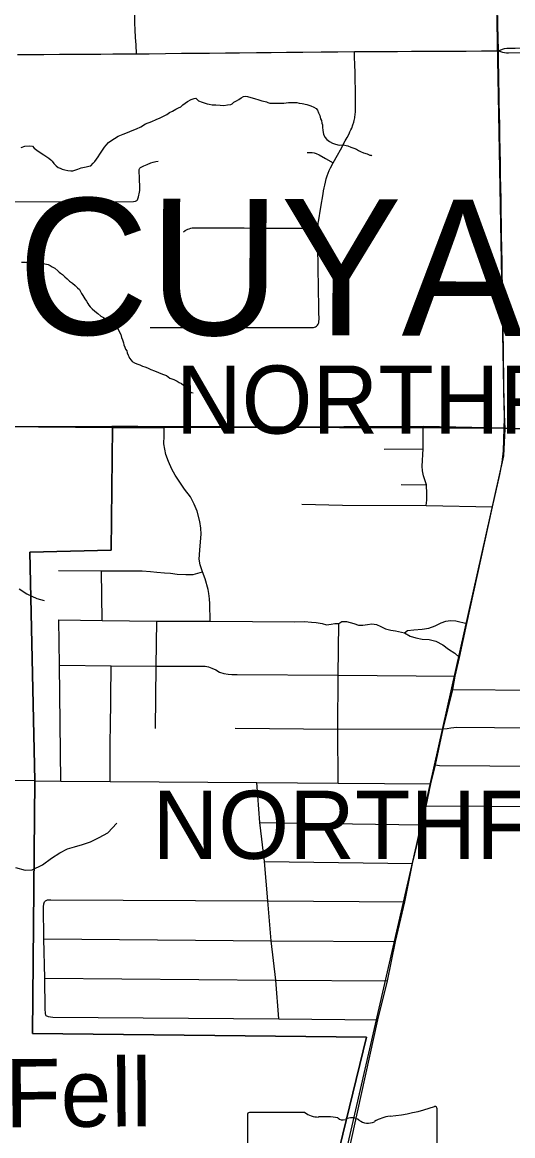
# Model space of a CAD drawing. Extents: x 0 to 34, y 0 to 22.
# Drawn here: x 3.992 to 4.674, y 14.366 to 15.914 of the extents above; entities that cross this region are included whole.
import ezdxf

# ---------------------------------------------------------------- set-up
doc = ezdxf.new("R2010")
doc.units = 0
for name, color, linetype in [('GM_X_City_Street', 7, 'Continuous'), ('GM_X_Corporation_Text', 7, 'Continuous'), ('GM_X_County_Road', 7, 'Continuous'), ('GM_X_County_Text', 7, 'Continuous'), ('GM_X_Minor_Lake_Text', 7, 'Continuous'), ('GM_X_Minor_River', 7, 'Continuous'), ('GM_X_Rail_Line', 7, 'Continuous'), ('GM_X_State_Route', 7, 'Continuous'), ('GM_X_State_Shield', 7, 'Continuous'), ('GM_X_Township_Road', 7, 'Continuous'), ('SH_Cut_Line', 7, 'Continuous')]:
    doc.layers.add(name, color=color, linetype=linetype)

msp = doc.modelspace()

# ---------------------------------------------------------------- linework, layer by layer
at = {"layer": 'GM_X_City_Street'}
for p, q in [((4.4951, 15.3209), (4.5493, 15.3211)), ((4.5189, 15.2716), (4.5539, 15.2711)), ((4.1025, 15.0825), (4.1017, 15.1517)), ((4.5905, 14.9868), (5.0641, 14.9831)), ((4.3223, 14.8018), (4.5473, 14.7985)), ((4.3287, 14.7474), (4.5346, 14.7449))]:
    msp.add_line(p, q, dxfattribs=at)
for points in [[(4.1505, 15.8705), (4.1498, 15.8829), (4.1492, 15.893), (4.1487, 15.9038), (4.1484, 15.913), (4.148, 15.9252), (4.1475, 15.9384), (4.1472, 15.9495), (4.1468, 15.9654), (4.1465, 15.9801), (4.1462, 15.9917), (4.1459, 16.0043), (4.1456, 16.0183), (4.1454, 16.0261), (4.1452, 16.028), (4.145, 16.0299), (4.1446, 16.0317), (4.144, 16.0335), (4.1434, 16.0347), (4.1428, 16.0358), (4.142, 16.0368), (4.1411, 16.0377), (4.1401, 16.0385)], [(4.4021, 15.493), (4.4031, 15.4944), (4.4036, 15.4955), (4.404, 15.4966), (4.4043, 15.4988), (4.4044, 15.5012), (4.4043, 15.5116), (4.4041, 15.5248), (4.4038, 15.5375), (4.4036, 15.5514), (4.4033, 15.5665), (4.403, 15.5815), (4.4027, 15.5937), (4.4025, 15.606), (4.4023, 15.6157), (4.4024, 15.6251), (4.4025, 15.6278), (4.4027, 15.6305), (4.403, 15.6327), (4.4032, 15.6348), (4.4035, 15.637), (4.4069, 15.6571), (4.4101, 15.6758), (4.4108, 15.6799), (4.4115, 15.684), (4.4123, 15.688), (4.4133, 15.6922), (4.4145, 15.6967), (4.4157, 15.7007), (4.4171, 15.7046), (4.4186, 15.7083), (4.4203, 15.7119), (4.424, 15.7187), (4.4299, 15.7296), (4.4341, 15.7371), (4.441, 15.7493), (4.4437, 15.7542), (4.4463, 15.7592), (4.4475, 15.7619), (4.4487, 15.7645), (4.4499, 15.7672), (4.4516, 15.7718), (4.4527, 15.7756), (4.4532, 15.7775), (4.4537, 15.7794), (4.4541, 15.7814), (4.4544, 15.7832), (4.4546, 15.785), (4.4549, 15.7868), (4.455, 15.7886), (4.4551, 15.7904), (4.4552, 15.7922), (4.4553, 15.7971), (4.4551, 15.8221), (4.4548, 15.8324), (4.4545, 15.8439), (4.4543, 15.8554), (4.454, 15.8656), (4.4539, 15.8734)], [(4.3879, 15.733), (4.3924, 15.7331), (4.3951, 15.733), (4.3975, 15.7327), (4.399, 15.7324), (4.4004, 15.7319), (4.4045, 15.7299), (4.4133, 15.7248), (4.424, 15.7187)], [(3.9667, 15.6647), (4.1461, 15.6652), (4.1491, 15.6655), (4.15, 15.6659), (4.1509, 15.6666), (4.1517, 15.6675), (4.1523, 15.6687), (4.1531, 15.6715), (4.1545, 15.678), (4.1549, 15.6804), (4.155, 15.6833), (4.1545, 15.6983), (4.1541, 15.7066), (4.1542, 15.7095), (4.1547, 15.7105), (4.1553, 15.7115), (4.1561, 15.7122), (4.1569, 15.7128), (4.1609, 15.7148), (4.1651, 15.7167), (4.1702, 15.7187), (4.1736, 15.7198), (4.1756, 15.7203), (4.1776, 15.7206), (4.1808, 15.721)], [(4.2158, 15.6229), (4.2183, 15.6247), (4.2201, 15.6257), (4.222, 15.6266), (4.2239, 15.6273), (4.2259, 15.6279), (4.2279, 15.6283), (4.2299, 15.6286), (4.234, 15.6287), (4.2471, 15.6286), (4.2639, 15.6285), (4.2822, 15.6284), (4.3001, 15.6283), (4.3162, 15.6282), (4.335, 15.6281), (4.3534, 15.628), (4.3721, 15.6279), (4.3884, 15.6278), (4.4025, 15.6278)], [(4.1694, 15.4901), (4.3947, 15.4898), (4.3966, 15.4901), (4.398, 15.4905), (4.3994, 15.491), (4.4008, 15.4918), (4.4021, 15.493)], [(4.2529, 15.0816), (4.2524, 15.1058), (4.252, 15.1125), (4.2513, 15.1201), (4.25, 15.1259), (4.246, 15.1403), (4.2422, 15.1501), (4.239, 15.1599), (4.2376, 15.1679), (4.2385, 15.1804), (4.2396, 15.1921), (4.2406, 15.2027), (4.2399, 15.2108), (4.2387, 15.2202), (4.235, 15.2345), (4.2307, 15.2442), (4.2254, 15.2543), (4.2173, 15.2651), (4.2044, 15.2845), (4.1996, 15.2928), (4.195, 15.3036), (4.1913, 15.3133), (4.1899, 15.3209), (4.1887, 15.3283), (4.1891, 15.3391), (4.1889, 15.3522)], [(4.5534, 15.2424), (4.5543, 15.2499), (4.5546, 15.2587), (4.5539, 15.2711), (4.5497, 15.2836), (4.5482, 15.2909), (4.5478, 15.2971), (4.5493, 15.3211), (4.5495, 15.3508)], [(4.3806, 15.2442), (4.4371, 15.2428), (4.5534, 15.2424), (4.646, 15.2405)], [(4.0418, 15.1521), (4.1017, 15.1517), (4.1586, 15.1517), (4.1699, 15.1508), (4.179, 15.1497), (4.1893, 15.149), (4.1977, 15.1485), (4.2071, 15.1472), (4.2191, 15.1465), (4.2291, 15.1465), (4.2422, 15.1501)], [(4.0423, 15.0834), (4.1025, 15.0825), (4.1788, 15.0816), (4.2529, 15.0816), (4.371, 15.0806), (4.3841, 15.0811), (4.3938, 15.0804), (4.4005, 15.0797), (4.4086, 15.0784), (4.4147, 15.0767), (4.4212, 15.0776), (4.4265, 15.0785), (4.4322, 15.0785), (4.4362, 15.0811), (4.4428, 15.0813), (4.4527, 15.0783), (4.4592, 15.076), (4.4652, 15.0762), (4.4719, 15.0769), (4.4779, 15.0778), (4.4843, 15.0769), (4.4903, 15.0744), (4.497, 15.0712), (4.5041, 15.0691), (4.5108, 15.0684), (4.5235, 15.0656), (4.5313, 15.061), (4.5391, 15.0583), (4.5477, 15.0566), (4.5576, 15.056), (4.5668, 15.0539), (4.5767, 15.049), (4.5845, 15.0428), (4.5935, 15.0371), (4.5999, 15.0311)], [(4.0452, 14.8592), (4.0432, 15.0204), (4.0423, 15.0834)], [(4.177, 14.9324), (4.1779, 15.0193), (4.1788, 15.0816)], [(4.4312, 14.8565), (4.4306, 14.9317), (4.431, 15.0064), (4.4322, 15.0785)], [(4.5235, 15.0656), (4.5274, 15.0686), (4.5361, 15.0698), (4.5479, 15.0705), (4.5571, 15.0721), (4.5661, 15.0751), (4.5744, 15.0792), (4.5808, 15.0815), (4.5875, 15.0827), (4.5947, 15.082), (4.6101, 15.0783)], [(4.0432, 15.0204), (4.1152, 15.0198), (4.1779, 15.0193), (4.2462, 15.0189), (4.2506, 15.018), (4.2553, 15.0164), (4.2607, 15.0138), (4.266, 15.0107), (4.272, 15.0087), (4.2778, 15.0078), (4.2831, 15.0075), (4.2907, 15.0073), (4.431, 15.0064), (4.594, 15.005)], [(4.1139, 14.8586), (4.1137, 14.9188), (4.1141, 14.931), (4.1152, 15.0198)], [(4.2878, 14.9331), (4.4306, 14.9317), (4.5771, 14.9322)], [(4.5771, 14.9322), (4.5829, 14.9325), (4.588, 14.9334), (4.596, 14.9343), (5.0664, 14.93)], [(4.5664, 14.8821), (4.5722, 14.8812), (4.7121, 14.8799), (4.8933, 14.879), (5.0666, 14.8763)], [(4.0094, 14.8598), (4.0452, 14.8592), (4.1139, 14.8586), (4.318, 14.8573), (4.4312, 14.8565), (4.5598, 14.8557)], [(4.3483, 14.5288), (4.3443, 14.5828), (4.3378, 14.6373), (4.3334, 14.6927), (4.3287, 14.7474), (4.3223, 14.8018), (4.318, 14.8573)], [(4.856, 14.5164), (4.8055, 14.5161), (4.8008, 14.5165), (4.7966, 14.517), (4.7908, 14.5192), (4.7859, 14.5221), (4.7821, 14.5265), (4.7801, 14.5321), (4.7799, 14.5392), (4.781, 14.6406), (4.7817, 14.7651), (4.7813, 14.7758), (4.7799, 14.7834), (4.7773, 14.7907), (4.7748, 14.7947), (4.7708, 14.8014), (4.7646, 14.8083), (4.7592, 14.8127), (4.7517, 14.817), (4.7437, 14.8205), (4.7357, 14.8223), (4.7245, 14.8234), (4.5535, 14.8247)], [(4.0245, 14.5334), (4.0238, 14.5368), (4.0234, 14.5421), (4.0229, 14.5852), (4.0214, 14.6399), (4.0209, 14.6844), (4.0216, 14.6886), (4.0223, 14.6913), (4.024, 14.6931)], [(4.024, 14.6931), (4.0269, 14.6942), (4.0312, 14.6944), (4.3334, 14.6927), (4.524, 14.6913)], [(4.0214, 14.6399), (4.3378, 14.6373), (4.5108, 14.6362)], [(4.0229, 14.5852), (4.3443, 14.5828), (4.4995, 14.5817)], [(4.0245, 14.5334), (4.0278, 14.5323), (4.0309, 14.5316), (4.0343, 14.5312), (4.3483, 14.5288), (4.4864, 14.5275)]]:
    msp.add_lwpolyline(points, dxfattribs=at)
at = {"layer": 'GM_X_County_Road'}
msp.add_line((4.1523, 15.3526), (4.1549, 15.3525), dxfattribs=at)
for points in [[(3.985, 15.8693), (4.0039, 15.8694), (4.0217, 15.8695), (4.0434, 15.8697), (4.0632, 15.8698), (4.081, 15.87), (4.101, 15.8701), (4.1176, 15.8702), (4.1381, 15.8704), (4.1505, 15.8705), (4.168, 15.8706), (4.1908, 15.8709), (4.213, 15.8711), (4.2332, 15.8713), (4.2522, 15.8714), (4.2743, 15.8717), (4.294, 15.8719), (4.3176, 15.8721), (4.3378, 15.8723), (4.3593, 15.8725), (4.3818, 15.8727), (4.4075, 15.873), (4.4307, 15.8732), (4.4539, 15.8734), (4.4736, 15.8735), (4.4929, 15.8736), (4.5135, 15.8738), (4.533, 15.8739), (4.5539, 15.874), (4.5741, 15.8741), (4.5914, 15.8742), (4.609, 15.8743), (4.6303, 15.8745), (4.654, 15.8746)], [(4.654, 15.8746), (4.6596, 15.877), (4.6624, 15.8779), (4.6655, 15.8783), (4.6775, 15.8784), (4.6955, 15.8785), (4.7114, 15.8786), (4.7292, 15.8787), (4.7462, 15.8788), (4.7626, 15.8789), (4.779, 15.879), (4.7958, 15.8792), (4.8137, 15.8793), (4.9176, 15.8796), (4.9411, 15.8797), (4.9626, 15.8797)], [(4.654, 15.8746), (4.6598, 15.8727), (4.6626, 15.8722), (4.6652, 15.8719), (4.6682, 15.8717), (4.8136, 15.8721), (4.9446, 15.8724), (4.9655, 15.8725)], [(3.8085, 15.3532), (3.8384, 15.3529), (3.8832, 15.3532), (3.9221, 15.3531), (3.9719, 15.3528), (4.032, 15.3522), (4.1163, 15.3526), (4.1523, 15.3526)], [(4.1549, 15.3525), (4.1567, 15.3525), (4.1806, 15.3522), (4.1889, 15.3522)], [(4.1889, 15.3522), (4.271, 15.3523), (4.3262, 15.3519), (4.3455, 15.3517), (4.3666, 15.3516), (4.3963, 15.3514), (4.4329, 15.351), (4.5495, 15.3508)], [(4.5495, 15.3508), (4.5819, 15.3506), (4.6282, 15.3504), (4.6622, 15.3502)]]:
    msp.add_lwpolyline(points, dxfattribs=at)
at = {"layer": 'GM_X_County_Text'}
for points in [[(2.1, 20.9), (2.1, 15.3556), (2.5967, 15.3568), (2.8413, 15.3568), (3.0143, 15.3554), (3.32, 15.3518), (3.6529, 15.3542), (3.8077, 15.3535), (4.1171, 15.3509), (4.1892, 15.3509), (4.3286, 15.3514), (4.5491, 15.3522), (4.6624, 15.3501), (5.0644, 15.3373), (5.4203, 15.3364), (5.4506, 15.3363), (5.4723, 15.3363), (5.5032, 15.3362), (5.5738, 15.336), (5.6184, 15.3359), (5.911, 15.3352), (6.0514, 15.3349), (6.6171, 15.3291), (8.9, 15.3047)], [(5.0601, 14.3351), (5.0736, 14.8415), (5.0745, 14.9887), (5.0644, 15.3373), (4.6624, 15.3501), (4.5491, 15.3522), (4.3286, 15.3514), (4.1892, 15.3509), (4.1171, 15.3509), (4.1154, 15.1803), (4.002, 15.1777), (4.0092, 14.8604), (4.0058, 14.5086), (4.4707, 14.5032), (4.4185, 14.2906)]]:
    msp.add_lwpolyline(points, dxfattribs=at)
msp.add_lwpolyline([(2.1, 15.3556), (2.1, 14.1), (4.3787, 14.1), (4.3725, 14.1373), (4.3676, 14.1533), (4.4185, 14.2906), (4.4707, 14.5032), (4.0058, 14.5086), (4.0092, 14.8604), (4.002, 15.1777), (4.1154, 15.1803), (4.1171, 15.3509), (3.8077, 15.3535), (3.6529, 15.3542), (3.32, 15.3518), (3.0143, 15.3554), (2.8413, 15.3568), (2.5967, 15.3568)], close=True, dxfattribs=at)
at = {"layer": 'GM_X_Minor_River'}
for points in [[(4.1059, 15.7406), (4.1081, 15.7433), (4.1115, 15.7472), (4.116, 15.7503), (4.1201, 15.7526), (4.125, 15.7561), (4.1318, 15.7588), (4.1378, 15.7612), (4.1443, 15.7639), (4.1507, 15.7663), (4.1567, 15.769), (4.1631, 15.7733), (4.1718, 15.7761), (4.1778, 15.7792), (4.1835, 15.7815), (4.188, 15.7839), (4.1925, 15.7862), (4.1963, 15.7886), (4.2005, 15.7909), (4.205, 15.7936), (4.2091, 15.7952), (4.2121, 15.7967), (4.2151, 15.7994), (4.2215, 15.8041), (4.2264, 15.8068), (4.2306, 15.8084), (4.2329, 15.8088), (4.2367, 15.805), (4.2417, 15.8032), (4.2462, 15.8017), (4.2489, 15.801), (4.2516, 15.8003), (4.2558, 15.7996), (4.2607, 15.7993), (4.2671, 15.799), (4.2721, 15.7986), (4.277, 15.7995), (4.2816, 15.7999), (4.2834, 15.8007), (4.2861, 15.803), (4.2898, 15.805), (4.2928, 15.8069), (4.2959, 15.8092), (4.2992, 15.8112), (4.3027, 15.8116), (4.3049, 15.8112), (4.316, 15.808), (4.3194, 15.8069), (4.3221, 15.8061), (4.3247, 15.805), (4.3274, 15.8047), (4.3293, 15.8039), (4.3312, 15.8036), (4.3331, 15.8025), (4.3362, 15.8017), (4.3392, 15.8018), (4.3426, 15.8018), (4.3487, 15.8019), (4.3555, 15.802), (4.362, 15.8025), (4.3677, 15.8025), (4.3707, 15.8029), (4.3734, 15.8026), (4.3768, 15.8019), (4.381, 15.8012), (4.3874, 15.8001), (4.3931, 15.7983), (4.3973, 15.7964), (4.4004, 15.7946), (4.4023, 15.7919), (4.4039, 15.7885), (4.4055, 15.7848), (4.4067, 15.7802), (4.4078, 15.7776), (4.4083, 15.7741), (4.4091, 15.7715), (4.4091, 15.7684), (4.4095, 15.7639), (4.4107, 15.7586), (4.4127, 15.7544), (4.4154, 15.7514), (4.4188, 15.7484), (4.4234, 15.7462), (4.4272, 15.7447), (4.4326, 15.7436), (4.4379, 15.7437), (4.4447, 15.7423), (4.4485, 15.7408), (4.4527, 15.7393), (4.4565, 15.7379), (4.4592, 15.736), (4.4623, 15.7345), (4.4661, 15.7327), (4.4714, 15.7312), (4.4749, 15.7297), (4.4768, 15.7294), (4.4779, 15.7286)], [(3.9901, 15.7403), (3.995, 15.7419), (4.0022, 15.7424), (4.0057, 15.742), (4.0083, 15.7394), (4.0118, 15.7364), (4.0164, 15.733), (4.0214, 15.73), (4.0256, 15.7274), (4.0286, 15.7252), (4.0313, 15.7229), (4.0333, 15.7211), (4.0356, 15.7177), (4.0386, 15.7147), (4.0417, 15.7124), (4.0444, 15.7113), (4.0471, 15.7102), (4.0509, 15.7091), (4.0551, 15.708), (4.0589, 15.7077), (4.0619, 15.7077), (4.0649, 15.7085), (4.0687, 15.7101), (4.0736, 15.7121), (4.0804, 15.7133), (4.0842, 15.7141), (4.0868, 15.7149), (4.0902, 15.7184), (4.0925, 15.7207), (4.0947, 15.7241), (4.0973, 15.7272), (4.0995, 15.7307), (4.1059, 15.7406)], [(3.9903, 15.5809), (3.9937, 15.5806), (3.996, 15.5806), (3.9983, 15.5803), (4.0009, 15.5799), (4.004, 15.58), (4.0081, 15.5797), (4.0123, 15.5797), (4.0161, 15.5798), (4.0207, 15.5791), (4.0275, 15.5776), (4.0306, 15.5761), (4.0333, 15.5743), (4.0367, 15.5724), (4.0409, 15.5687), (4.0428, 15.5668), (4.0448, 15.5653), (4.0474, 15.5634), (4.0509, 15.5604), (4.054, 15.5574), (4.0574, 15.5544), (4.0613, 15.5514), (4.0651, 15.5481), (4.0686, 15.5451), (4.0712, 15.5428), (4.0724, 15.5402), (4.074, 15.5371), (4.0759, 15.5345), (4.0774, 15.5322), (4.0786, 15.5296), (4.0809, 15.5266), (4.0829, 15.5232), (4.084, 15.5209), (4.086, 15.5187), (4.089, 15.516), (4.0925, 15.5127), (4.0967, 15.5093), (4.1009, 15.5059), (4.1048, 15.5037), (4.1094, 15.5007), (4.1124, 15.4985), (4.1159, 15.4962), (4.1193, 15.4936), (4.1216, 15.4917), (4.1239, 15.4891), (4.1286, 15.4804), (4.1298, 15.4762), (4.131, 15.4728), (4.1322, 15.4687), (4.133, 15.466), (4.1341, 15.4626), (4.1353, 15.46), (4.1369, 15.4573), (4.1377, 15.4547), (4.1388, 15.4516), (4.14, 15.4494), (4.1408, 15.4475), (4.1431, 15.4445), (4.1443, 15.4426), (4.1477, 15.4407), (4.1511, 15.4392), (4.1549, 15.4378), (4.1588, 15.4363), (4.1622, 15.4352), (4.166, 15.4337), (4.1706, 15.4315), (4.1755, 15.4297), (4.1813, 15.4275), (4.1866, 15.4252), (4.1923, 15.423), (4.1969, 15.4197), (4.2026, 15.4175), (4.2069, 15.4152), (4.2099, 15.4137), (4.213, 15.4119), (4.2157, 15.4096), (4.218, 15.4078), (4.2203, 15.4055), (4.2222, 15.4033), (4.2249, 15.401), (4.2272, 15.3995), (4.2294, 15.3992)], [(3.9872, 15.1268), (3.9979, 15.1197), (4.0119, 15.1134), (4.0222, 15.1105)], [(3.9823, 14.7392), (3.9956, 14.7356), (4.0055, 14.7361), (4.0198, 14.7427), (4.0322, 14.7523), (4.0439, 14.7597), (4.0544, 14.7651), (4.0643, 14.7679), (4.0752, 14.7711), (4.0865, 14.775), (4.0986, 14.7808), (4.1107, 14.7874), (4.123, 14.8009)]]:
    msp.add_lwpolyline(points, dxfattribs=at)
at = {"layer": 'GM_X_Rail_Line'}
for points in [[(4.6634, 15.349), (4.6621, 15.3797), (4.6383, 16.6765)], [(4.3502, 14.1), (4.411, 14.2385), (4.436, 14.3173), (4.5399, 14.7696), (4.6617, 15.3116), (4.6634, 15.349)]]:
    msp.add_lwpolyline(points, dxfattribs=at)
at = {"layer": 'GM_X_State_Route'}
msp.add_line((4.4402, 14.3177), (4.4581, 14.3992), dxfattribs=at)
for points in [[(4.654, 15.8746), (4.6537, 15.8935), (4.6534, 15.9087), (4.6532, 15.9238)], [(4.6622, 15.3502), (4.6625, 15.3637), (4.6623, 15.3748), (4.6621, 15.3874), (4.6617, 15.4099), (4.6615, 15.4244), (4.6612, 15.4442), (4.6609, 15.4631), (4.6607, 15.4782), (4.6604, 15.4976), (4.6601, 15.5157), (4.6599, 15.5296), (4.6596, 15.5485), (4.6593, 15.5647), (4.659, 15.5816), (4.6588, 15.599), (4.6584, 15.6197), (4.6582, 15.6329), (4.6579, 15.6501), (4.6576, 15.6692), (4.6573, 15.6838), (4.657, 15.7023), (4.6567, 15.7189), (4.6564, 15.7363), (4.6561, 15.7554), (4.6558, 15.7708), (4.6555, 15.7871), (4.6552, 15.8024), (4.655, 15.8171), (4.6548, 15.8299), (4.6545, 15.8423), (4.6543, 15.8578), (4.654, 15.8746)], [(4.4581, 14.3992), (4.4864, 14.5275), (4.4995, 14.5817), (4.5108, 14.6362), (4.524, 14.6913), (4.5346, 14.7449), (4.5473, 14.7985), (4.5535, 14.8247), (4.5598, 14.8557), (4.5664, 14.8821), (4.5771, 14.9322), (4.5905, 14.9868), (4.594, 15.005), (4.5999, 15.0311), (4.6101, 15.0783), (4.646, 15.2405), (4.6559, 15.2856), (4.6592, 15.3022), (4.661, 15.3183), (4.6622, 15.3502)]]:
    msp.add_lwpolyline(points, dxfattribs=at)
at = {"layer": 'GM_X_State_Shield'}
for p, q in [((4.3848, 14.3987), (4.3075, 14.3987)), ((4.5686, 14.299), (4.5686, 14.4037)), ((4.3049, 14.3953), (4.3049, 14.1951))]:
    msp.add_line(p, q, dxfattribs=at)
for centre, radius, start, end in [((4.308, 14.3957), 0.00305, 98.1301, 188.1301), ((4.4031, 14.4219), 0.0296, 231.6195, 271.1119), ((4.4747, 14.6715), 0.2796, 275.8445, 288.9065), ((4.5657, 14.4041), 0.00294, 351.8621, 97.738), ((4.413, 14.2864), 0.1064, 80.4867, 94.9883), ((4.4371, 14.3967), 0.00855, 219.7921, 297.1024), ((4.4497, 14.3736), 0.0178, 54.4667, 119.1411), ((4.4726, 14.4053), 0.0214, 233.8562, 294.8282), ((4.5104, 14.3376), 0.0563, 97.3462, 120.7689)]:
    msp.add_arc(centre, radius, start, end, dxfattribs=at)
at = {"layer": 'GM_X_Township_Road'}
msp.add_line((4.1523, 15.3526), (4.1549, 15.3525), dxfattribs=at)
for points in [[(3.8085, 15.3532), (3.8384, 15.3529), (3.8832, 15.3532), (3.9221, 15.3531), (3.9719, 15.3528), (4.032, 15.3522), (4.1163, 15.3526), (4.1523, 15.3526)], [(4.1549, 15.3525), (4.1567, 15.3525), (4.1806, 15.3522), (4.1889, 15.3522)], [(4.1889, 15.3522), (4.271, 15.3523), (4.3262, 15.3519), (4.3455, 15.3517), (4.3666, 15.3516), (4.3963, 15.3514), (4.4329, 15.351), (4.5495, 15.3508)], [(4.5495, 15.3508), (4.5819, 15.3506), (4.6282, 15.3504), (4.6622, 15.3502)], [(4.0094, 14.8598), (3.9115, 14.861), (3.821, 14.8613), (3.6366, 14.8632), (3.628, 14.8639), (3.4647, 14.8648), (3.38, 14.8663), (3.1683, 14.8681), (3.1666, 14.8681), (3.0076, 14.867), (2.8745, 14.8645)]]:
    msp.add_lwpolyline(points, dxfattribs=at)
at = {"layer": 'SH_Cut_Line'}
for points in [[(2.1, 20.9), (2.1, 15.3556), (2.5967, 15.3568), (2.8413, 15.3568), (3.0143, 15.3554), (3.32, 15.3518), (3.6529, 15.3542), (3.8077, 15.3535), (4.1171, 15.3509), (4.1892, 15.3509), (4.3286, 15.3514), (4.5491, 15.3522), (4.6624, 15.3501), (5.0644, 15.3373), (5.4203, 15.3364), (5.4506, 15.3363), (5.4723, 15.3363), (5.5032, 15.3362), (5.5738, 15.336), (5.6184, 15.3359), (5.911, 15.3352), (6.0514, 15.3349), (6.6171, 15.3291), (8.9, 15.3047)], [(8.9, 15.3047), (6.6171, 15.3291), (6.0514, 15.3349), (5.911, 15.3352), (5.6184, 15.3359), (5.5738, 15.336), (5.5032, 15.3362), (5.4723, 15.3363), (5.4506, 15.3363), (5.4203, 15.3364), (5.0644, 15.3373), (4.6624, 15.3501), (4.5491, 15.3522), (4.3286, 15.3514), (4.1892, 15.3509), (4.1171, 15.3509), (3.8077, 15.3535), (3.6529, 15.3542), (3.32, 15.3518), (3.0143, 15.3554), (2.8413, 15.3568), (2.5967, 15.3568), (2.1, 15.3556)]]:
    msp.add_lwpolyline(points, dxfattribs=at)

# ---------------------------------------------------------------- texts
at = {"layer": 'GM_X_Corporation_Text'}
for p in [(4.2053, 15.3424), (4.1728, 14.7512)]:
    msp.add_text('NORTHFIELD', height=0.0947, rotation=0, dxfattribs=at).set_placement(p)
at = {"layer": 'GM_X_County_Text'}
msp.add_text('CUYAHOGA COUNTY', height=0.189394, rotation=359.8191, dxfattribs=at).set_placement((3.9846, 15.4804))
at = {"layer": 'GM_X_Minor_Lake_Text'}
msp.add_text('Fell', height=0.09475, rotation=0.4156, dxfattribs=at).set_placement((3.9678, 14.378))

doc.saveas('drawing.dxf')
